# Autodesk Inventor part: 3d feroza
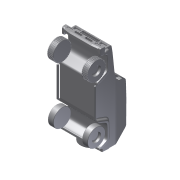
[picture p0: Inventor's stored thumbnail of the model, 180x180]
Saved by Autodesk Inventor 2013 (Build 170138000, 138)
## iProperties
Created: 2012-09
Part Number: 3d feroza
Material: Generico
Document SubType Name: Modeling
Designer: Massimo Pizzirani
Density: 1 g/cm^3
Author: Massimo Pizzirani
Norme di conversione: STEP AP214IS
Nome file: C:\Users\Darren\Desktop\just downloaded\3d feroza.stp
Preprocessore: Autodesk Inventor 2012
Postprocessore: Build: 138, Release: 2013 RTM - Date: Thu 03/01/2012
Unità inviate: millimetro
Incertezza: 0.01
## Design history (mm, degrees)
node "3d feroza1"
body "Solid2"
node "Solid2_1"
node "Solid2_2"
node "Solid2_3"
node "Solid2_4"
body "Solid3"
node "Solid3_1"
node "Solid3_2"
node "Solid3_3"
node "Solid3_4"
node "Solid3_5"
node "Solid3_6"
node "Solid3_7"
node "Solid3_8"
node "Solid3_9"
node "Solid3_10"
node "Solid3_11"
node "Solid3_12"
node "Solid3_13"
node "Solid3_14"
node "Solid3_15"
node "Solid3_16"
node "Solid3_17"
node "Solid3_18"
node "Solid3_19"
node "Solid3_20"
node "Solid3_21"
node "Solid3_22"
node "Solid3_23"
node "Solid3_24"
node "Solid3_25"
node "Solid3_26"
node "Solid3_27"
node "Solid3_28"
node "Solid3_29"
node "Solid3_30"
node "Solid3_31"
node "Solid3_32"
node "Solid3_33"
node "Solid3_34"
node "Solid3_35"
node "Solid3_36"
node "Solid3_37"
node "Solid3_38"
node "Solid3_39"
node "Solid3_40"
node "Solid3_41"
node "Solid3_42"
node "Solid3_43"
node "Solid3_44"
node "Solid3_45"
node "Solid3_46"
node "Solid3_47"
node "Solid3_48"
node "Solid3_49"
node "Solid3_50"
node "Solid3_51"
node "Solid3_52"
node "Solid3_53"
node "Solid3_54"
node "Solid3_55"
node "Solid3_56"
node "Solid3_57"
node "Solid3_58"
node "Solid3_59"
node "Solid3_60"
node "Solid3_61"
node "Solid3_62"
node "Solid3_63"
node "Solid3_64"
node "Solid3_65"
node "Solid3_66"
node "Solid3_67"
node "Solid3_68"
node "Solid3_69"
node "Solid3_70"
node "Solid3_71"
node "Solid3_72"
node "Solid3_73"
node "Solid3_74"
node "Solid3_75"
node "Solid3_76"
node "Solid3_77"
node "Solid3_78"
node "Solid3_79"
node "Solid3_80"
node "Solid3_81"
node "Solid3_82"
node "Solid3_83"
node "Solid3_84"
node "Solid3_85"
node "Solid3_86"
node "Solid3_87"
node "Solid3_88"
node "Solid3_89"
node "Solid3_90"
node "Solid3_91"
node "Solid3_92"
node "Solid3_93"
node "Solid3_94"
node "Solid3_95"
node "Solid3_96"
node "Solid3_97"
node "Solid3_98"
node "Solid3_99"
node "Solid3_100"
node "Solid3_101"
node "Solid3_102"
node "Solid3_103"
node "Solid3_104"
node "Solid3_105"
node "Solid3_106"
node "Solid3_107"
node "Solid3_108"
node "Solid3_109"
node "Solid3_110"
node "Solid3_111"
node "Solid3_112"
node "Solid3_113"
node "Solid3_114"
node "Solid3_115"
node "Solid3_116"
node "Solid3_117"
node "Solid3_118"
node "Solid3_119"
node "Solid3_120"
node "Solid3_121"
node "Solid3_122"
node "Solid3_123"
node "Solid3_124"
node "Solid3_125"
node "Solid3_126"
node "Solid3_127"
node "Solid3_128"
node "Solid3_129"
node "Solid3_130"
node "Solid3_131"
node "Solid3_132"
node "Solid3_133"
node "Solid3_134"
node "Solid3_135"
node "Solid3_136"
node "Solid3_137"
node "Solid3_138"
node "Solid3_139"
node "Solid3_140"
node "Solid3_141"
node "Solid3_142"
node "Solid3_143"
node "Solid3_144"
node "Solid3_145"
node "Solid3_146"
node "Solid3_147"
node "Solid3_148"
node "Solid3_149"
node "Solid3_150"
node "Solid3_151"
node "Solid3_152"
node "Solid3_153"
node "Solid3_154"
node "Solid3_155"
node "Solid3_156"
node "Solid3_157"
node "Solid3_158"
node "Solid3_159"
node "Solid3_160"
node "Solid3_161"
node "Solid3_162"
node "Solid3_163"
node "Solid3_164"
node "Solid3_165"
node "Solid3_166"
node "Solid3_167"
node "Solid3_168"
node "Solid3_169"
node "Solid3_170"
node "Solid3_171"
node "Solid3_172"
node "Solid3_173"
node "Solid3_174"
node "Solid3_175"
node "Solid3_176"
node "Solid3_177"
node "Solid3_178"
node "Solid3_179"
node "Solid3_180"
node "Solid3_181"
node "Solid3_182"
node "Solid3_183"
node "Solid3_184"
node "Solid3_185"
node "Solid3_186"
node "Solid3_187"
node "Solid3_188"
node "Solid3_189"
node "Solid3_190"
node "Solid3_191"
node "Solid3_192"
node "Solid3_193"
node "Solid3_194"
node "Solid3_195"
node "Solid3_196"
node "Solid3_197"
node "Solid3_198"
node "Solid3_199"
node "Solid3_200"
node "Solid3_201"
node "Solid3_202"
node "Solid3_203"
node "Solid3_204"
node "Solid3_205"
node "Solid3_206"
node "Base1"
node "Base2"
node "Base3"
node "Base4"
node "Base5"
node "Base6"
node "Base7"
node "Base8"
node "Base9"
node "Base10"
node "Base11"
node "Base12"
node "Base13"
node "Base14"
node "Base15"
node "Base16"
node "Base17"
node "Base18"
node "Base19"
node "Base20"
node "Base21"
node "Base22"
node "Base23"
node "Base24"
node "Base25"
node "Base26"
node "Base27"
node "Base28"
node "Base29"
node "Base30"
node "Base31"
node "Base32"
node "Base33"
node "Base34"
node "Base35"
node "Base36"
node "Base37"
node "Base38"
node "Base39"
node "Base40"
node "Base41"
node "Base42"
node "Base43"
node "Base44"
node "Base45"
node "Base46"
node "Base47"
node "Base48"
node "Base49"
node "Base50"
node "Base51"
node "Base52"
node "Base53"
node "Base54"
node "Base55"
node "Base56"
node "Base57"
node "Base58"
node "Base59"
node "Base60"
node "Base61"
node "Base62"
node "Base63"
node "Base64"
node "Base65"
node "Base66"
node "Base67"
node "Base68"
node "Base69"
node "Base70"
node "Base71"
node "Base72"
node "Base73"
node "Base74"
node "Base75"
node "Base76"
node "Base77"
node "Base78"
node "Base79"
node "Base80"
node "Base81"
node "Base82"
node "Base83"
node "Base84"
node "Base85"
node "Base86"
node "Base87"
node "Base88"
node "Base89"
node "Base90"
node "Base91"
node "Base92"
node "Base93"
node "Base94"
node "Base95"
node "Base96"
node "Base97"
node "Base98"
node "Base99"
node "Base100"
node "Base101"
node "Base102"
node "Base103"
node "Base104"
node "Base105"
node "Base106"
node "Base107"
node "Base108"
node "Base109"
node "Base110"
node "Base111"
node "Base112"
node "Base113"
node "Base114"
node "Base115"
node "Base116"
node "Base117"
node "Base118"
node "Base119"
node "Base120"
node "Base121"
node "Base122"
node "Base123"
node "Base124"
node "Base125"
node "Base126"
node "Base127"
node "Base128"
node "Base129"
node "Base130"
node "Base131"
node "Base132"
node "Base133"
node "Base134"
node "Base135"
node "Base136"
node "Base137"
node "Base138"
node "Base139"
node "Base140"
node "Base141"
node "Base142"
node "Base143"
node "Base144"
node "Base145"
node "Base146"
node "Base147"
node "Base148"
node "Base149"
node "Base150"
node "Base151"
node "Base152"
node "Base153"
node "Base154"
node "Base155"
node "Base156"
node "Base157"
node "Base158"
node "Base159"
node "Base160"
node "Base161"
node "Base162"
node "Base163"
node "Base164"
node "Base165"
node "Base166"
node "Base167"
node "Base168"
node "Base169"
node "Base170"
node "Base171"
node "Base172"
node "Base173"
node "Base174"
node "Base175"
node "Base176"
node "Base177"
node "Base178"
node "Base179"
node "Base180"
node "Base181"
node "Base182"
node "Base183"
node "Base184"
node "Base185"
node "Base186"
node "Base187"
node "Base188"
node "Base189"
node "Base190"
node "Base191"
node "Base192"
node "Base193"
node "Base194"
node "Base195"
node "Base196"
node "Base197"
node "Base198"
node "Base199"
node "Base200"
node "Base201"
node "Base202"
node "Base203"
node "Base204"
node "Base205"
node "Base206"
node "Base207"
node "Base208"
node "Base209"
node "Base210"
node "Base211"
node "Base212"
